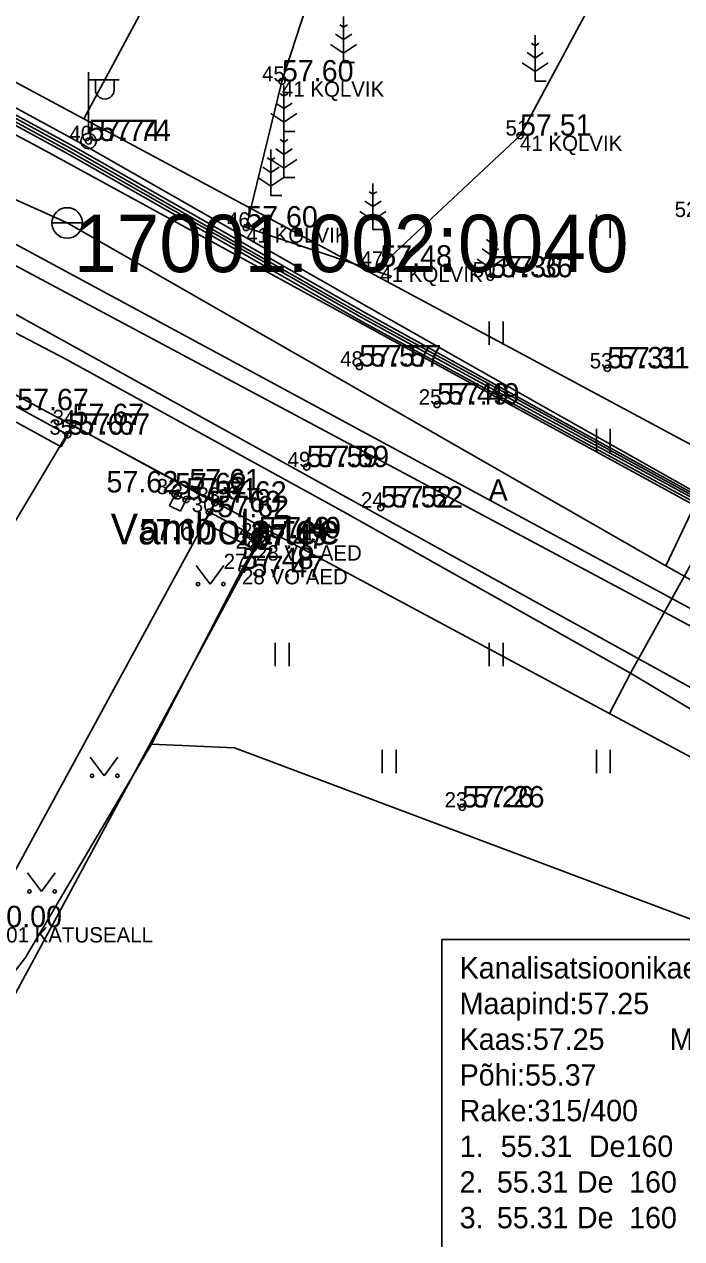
# Model space of a CAD drawing. Extents: x 640891 to 641083, y 6456526 to 6456669.
# Drawn here: x 640928.85 to 640950.33, y 6456556.9 to 6456596.6 of the extents above; entities that cross this region are included whole.
import ezdxf

# ---------------------------------------------------------------- set-up
doc = ezdxf.new("R2010")
doc.units = 0
for name, color, linetype in [('100koma2', 7, 'Continuous'), ('ABIJOONIS', 7, 'Continuous'), ('AED', 7, 'Continuous'), ('HALJASTUS', 7, 'Continuous'), ('KORGUS', 7, 'Continuous'), ('KPKAABEL', 7, 'Continuous'), ('KTRASS', 7, 'Continuous'), ('MOOTKORG', 7, 'Continuous'), ('MOOTMPUNKT', 7, 'Continuous'), ('MOOTNR', 7, 'Continuous'), ('MOOTPIIR', 7, 'Continuous'), ('MPKAABEL', 7, 'Continuous'), ('PIIR', 7, 'Continuous'), ('POST', 7, 'Continuous'), ('PUU', 7, 'Continuous'), ('SITRASS', 7, 'Continuous'), ('SKTRASS', 7, 'Continuous'), ('TEE', 7, 'Continuous'), ('VKAEV', 7, 'Continuous'), ('VTRASS', 7, 'Continuous')]:
    doc.layers.add(name, color=color, linetype=linetype)

msp = doc.modelspace()

# ---------------------------------------------------------------- linework, layer by layer
at = {"layer": 'ABIJOONIS'}
msp.add_lwpolyline([(640942.489, 6456566.685), (640951.949, 6456566.685), (640951.949, 6456555.319), (640942.489, 6456555.319)], close=True, dxfattribs=at)
at = {"layer": 'AED'}
for p, q in [((640920.739, 6456587.89), (640930.051, 6456582.793)), ((640930.051, 6456582.793), (640930.267, 6456583.186)), ((640933.59, 6456580.856), (640933.773, 6456581.238)), ((640933.59, 6456580.856), (640933.952, 6456580.683)), ((640933.952, 6456580.683), (640934.135, 6456581.065))]:
    msp.add_line(p, q, dxfattribs=at)
for points in [[(640930.267, 6456583.186), (640921.076, 6456588.216)], [(640930.267, 6456583.186), (640921.076, 6456588.216)], [(640934.135, 6456581.065), (640933.773, 6456581.238)], [(640936.327, 6456579.459), (640936.507, 6456579.796), (640934.895, 6456580.654), (640934.714, 6456580.318)], [(640936.327, 6456579.459), (640934.714, 6456580.318)], [(640936.397, 6456579.53), (640935.963, 6456578.793), (640933.007, 6456573.069)]]:
    msp.add_lwpolyline(points, dxfattribs=at)
at = {"layer": 'HALJASTUS'}
for p, q in [((640947.545, 6456590.381), (640947.545, 6456589.619)), ((640948, 6456590.381), (640948, 6456589.619)), ((640944.045, 6456586.881), (640944.045, 6456586.119)), ((640944.5, 6456586.881), (640944.5, 6456586.119)), ((640947.545, 6456583.381), (640947.545, 6456582.619)), ((640948, 6456583.381), (640948, 6456582.619)), ((640934.462, 6456578.908), (640934.925, 6456578.301)), ((640934.925, 6456578.301), (640935.371, 6456578.908)), ((640937.045, 6456576.381), (640937.045, 6456575.619)), ((640937.5, 6456576.381), (640937.5, 6456575.619)), ((640944.045, 6456576.381), (640944.045, 6456575.619)), ((640944.5, 6456576.381), (640944.5, 6456575.619)), ((640940.545, 6456572.881), (640940.545, 6456572.119)), ((640941, 6456572.881), (640941, 6456572.119)), ((640947.545, 6456572.881), (640947.545, 6456572.119)), ((640948, 6456572.881), (640948, 6456572.119)), ((640930.999, 6456572.642), (640931.462, 6456572.035)), ((640931.462, 6456572.035), (640931.908, 6456572.642)), ((640928.95, 6456568.859), (640929.413, 6456568.252)), ((640929.413, 6456568.252), (640929.859, 6456568.859))]:
    msp.add_line(p, q, dxfattribs=at)
msp.add_lwpolyline([(640940.859, 6456588.363), (640936.098, 6456589.959), (640937.267, 6456594.734), (640939.119, 6456600.434), (640944.153, 6456613.282), (640950.33, 6456623.315), (640954.177, 6456630.888), (640962.196, 6456639.436), (640963.998, 6456638.677), (640968.745, 6456632.01), (640966.503, 6456625.352), (640963.655, 6456626.075), (640962.794, 6456629.058), (640958.598, 6456629.914), (640954.818, 6456622.648), (640946.439, 6456612.875), (640948.12, 6456609.151), (640945.862, 6456604.895), (640949.763, 6456601.734), (640945.05, 6456592.964), (640940.483, 6456588.68)], dxfattribs=at)
for centre in [(640934.524, 6456578.301), (640935.353, 6456578.301), (640931.061, 6456572.035), (640931.89, 6456572.035), (640929.012, 6456568.252), (640929.841, 6456568.252)]:
    msp.add_circle(centre, 0.055, dxfattribs=at)
at = {"layer": 'KORGUS'}
for centre in [(640930.945, 6456592.786), (640944.075, 6456588.332), (640939.794, 6456585.413), (640947.904, 6456585.354), (640942.339, 6456584.172), (640930.423, 6456583.498), (640930.267, 6456583.186), (640938.078, 6456582.125), (640933.773, 6456581.238), (640934.135, 6456581.065), (640934.895, 6456580.654), (640935.08, 6456580.963), (640940.499, 6456580.804), (640936.327, 6456579.459), (640936.507, 6456579.796), (640943.159, 6456570.998)]:
    msp.add_circle(centre, 0.1, dxfattribs=at)
at = {"layer": 'KPKAABEL'}
msp.add_lwpolyline([(640977.507, 6456566.281), (640976.27, 6456566.95), (640967.49, 6456572.43), (640959.27, 6456576.625), (640951.05, 6456580.82), (640939.86, 6456586.9), (640935.075, 6456589.63), (640930.29, 6456592.36), (640924.23, 6456595.65), (640919.26, 6456598.135), (640914.117, 6456600.706)], dxfattribs=at)
at = {"layer": 'KTRASS'}
msp.add_lwpolyline([(640955.081, 6456575.091), (640928.16, 6456589.63)], dxfattribs=at)
at = {"layer": 'MOOTMPUNKT'}
for centre in [(640937.267, 6456594.734), (640945.05, 6456592.964), (640930.945, 6456592.786), (640936.098, 6456589.959), (640940.483, 6456588.68), (640944.075, 6456588.332), (640939.794, 6456585.413), (640947.904, 6456585.354), (640942.339, 6456584.172), (640930.423, 6456583.498), (640930.267, 6456583.186), (640938.078, 6456582.125), (640933.773, 6456581.238), (640934.135, 6456581.065), (640934.895, 6456580.654), (640935.08, 6456580.963), (640940.499, 6456580.804), (640936.327, 6456579.459), (640936.421, 6456579.57), (640936.507, 6456579.796), (640935.963, 6456578.793), (640943.159, 6456570.998)]:
    msp.add_circle(centre, 0.1, dxfattribs=at)
at = {"layer": 'MOOTPIIR'}
msp.add_lwpolyline([(640976.662, 6456538.007), (640959.29, 6456546.142), (640961.328, 6456555.553), (640965.053, 6456562.959), (640957.364, 6456564.816), (640935.712, 6456572.952), (640933.007, 6456573.069), (640928.881, 6456566.092), (640925.582, 6456561.827), (640921.958, 6456562.765), (640911.417, 6456572.885), (640912.029, 6456574.013), (640921.076, 6456588.216), (640912.945, 6456593.7), (640910.627, 6456595.318), (640915.929, 6456603.505), (640924.706, 6456598.502), (640938.233, 6456631.58)], dxfattribs=at)
at = {"layer": 'MPKAABEL'}
for points in [[(640914.394, 6456601.133), (640919.49, 6456598.58), (640924.46, 6456596.09), (640927.495, 6456594.445), (640930.53, 6456592.8), (640935.32, 6456590.07), (640940.11, 6456587.34), (640945.625, 6456584.22), (640951.14, 6456581.1), (640953.87, 6456579.745), (640956.6, 6456578.39), (640957.06, 6456579.17)], [(640914.173, 6456600.793), (640919.31, 6456598.225), (640924.28, 6456595.74), (640927.31, 6456594.095), (640930.34, 6456592.45), (640935.125, 6456589.72), (640939.91, 6456586.99), (640945.495, 6456583.945), (640951.08, 6456580.9), (640959.31, 6456576.71), (640967.54, 6456572.52), (640971.93, 6456569.78), (640976.32, 6456567.04), (640977.56, 6456566.369)], [(640977.608, 6456566.451), (640976.37, 6456567.12), (640971.98, 6456569.865), (640967.59, 6456572.61), (640959.355, 6456576.785), (640951.12, 6456580.96), (640945.54, 6456584.015), (640939.96, 6456587.07), (640935.175, 6456589.8), (640930.39, 6456592.53), (640927.355, 6456594.18), (640924.32, 6456595.83), (640919.35, 6456598.315), (640914.227, 6456600.876)], [(640977.66, 6456566.54), (640976.42, 6456567.21), (640972.03, 6456569.95), (640967.64, 6456572.69), (640959.395, 6456576.855), (640951.15, 6456581.02), (640945.58, 6456584.09), (640940.01, 6456587.16), (640935.225, 6456589.89), (640930.44, 6456592.62), (640927.405, 6456594.27), (640924.37, 6456595.92), (640919.4, 6456598.405), (640914.283, 6456600.963)]]:
    msp.add_lwpolyline(points, dxfattribs=at)
at = {"layer": 'PIIR'}
for points in [[(640930.79, 6456593.51), (640904.36, 6456607.7), (640935.64, 6456665.95), (640960.76, 6456649.34)], [(640957.22, 6456579.32), (640930.79, 6456593.51), (640960.76, 6456649.34), (640985.89, 6456632.73)]]:
    msp.add_lwpolyline(points, close=True, dxfattribs=at)
for points in [[(640890.598, 6456615.08), (640904.36, 6456607.7), (640930.79, 6456593.51), (640957.22, 6456579.32), (640983.63, 6456565.13), (641002.905, 6456555.058)], [(640993.023, 6456550.09), (640989.66, 6456551.83), (640963.18, 6456565.91), (640936.74, 6456580.1), (640910.31, 6456594.28), (640890.598, 6456604.875)], [(640890.598, 6456557.721), (640910.31, 6456594.28), (640936.74, 6456580.1), (640907.494, 6456525.865)], [(640907.494, 6456525.865), (640936.74, 6456580.1), (640963.18, 6456565.91), (640941.583, 6456525.865)]]:
    msp.add_lwpolyline(points, dxfattribs=at)
at = {"layer": 'POST'}
for p, q in [((640930.945, 6456593.036), (640930.945, 6456595.036)), ((640930.945, 6456594.786), (640931.945, 6456594.786)), ((640931.172, 6456594.465), (640931.172, 6456594.786)), ((640931.785, 6456594.465), (640931.785, 6456594.786)), ((640930.945, 6456592.786), (640930.945, 6456592.786))]:
    msp.add_line(p, q, dxfattribs=at)
msp.add_circle((640930.945, 6456592.786), 0.25, dxfattribs=at)
msp.add_arc((640931.478, 6456594.465), 0.306, 180, 0, dxfattribs=at)
at = {"layer": 'PUU'}
for p, q in [((640939.282, 6456596.856), (640939.282, 6456595.356)), ((640939.282, 6456596.106), (640939.016, 6456596.283)), ((640939.282, 6456596.506), (640939.158, 6456596.589)), ((640939.407, 6456596.589), (640939.282, 6456596.506)), ((640939.549, 6456596.283), (640939.282, 6456596.106)), ((640945.545, 6456596.249), (640945.545, 6456594.749)), ((640938.858, 6456595.945), (640939.282, 6456595.662)), ((640939.282, 6456595.662), (640939.707, 6456595.945)), ((640945.545, 6456595.899), (640945.42, 6456595.982)), ((640945.669, 6456595.982), (640945.545, 6456595.899)), ((640945.545, 6456595.499), (640945.278, 6456595.677)), ((640945.811, 6456595.677), (640945.545, 6456595.499)), ((640939.642, 6456595.356), (640939.282, 6456595.356)), ((640945.12, 6456595.339), (640945.545, 6456595.056)), ((640945.545, 6456595.056), (640945.969, 6456595.339)), ((640945.905, 6456594.749), (640945.545, 6456594.749)), ((640937.333, 6456594.249), (640937.209, 6456594.332)), ((640937.333, 6456594.599), (640937.333, 6456593.099)), ((640937.458, 6456594.332), (640937.333, 6456594.249)), ((640937.333, 6456593.849), (640937.066, 6456594.027)), ((640937.6, 6456594.027), (640937.333, 6456593.849)), ((640936.909, 6456593.688), (640937.333, 6456593.405)), ((640937.333, 6456593.405), (640937.757, 6456593.688)), ((640937.333, 6456593.099), (640937.333, 6456591.599)), ((640937.693, 6456593.099), (640937.333, 6456593.099)), ((640937.333, 6456592.749), (640937.209, 6456592.832)), ((640937.458, 6456592.832), (640937.333, 6456592.749)), ((640936.909, 6456592.16), (640936.784, 6456592.243)), ((640936.909, 6456592.51), (640936.909, 6456591.01)), ((640937.033, 6456592.243), (640936.909, 6456592.16)), ((640937.333, 6456592.349), (640937.066, 6456592.527)), ((640937.6, 6456592.527), (640937.333, 6456592.349)), ((640936.909, 6456591.76), (640936.642, 6456591.937)), ((640936.909, 6456592.188), (640937.333, 6456591.905)), ((640937.175, 6456591.937), (640936.909, 6456591.76)), ((640937.333, 6456591.905), (640937.757, 6456592.188)), ((640936.485, 6456591.599), (640936.909, 6456591.316)), ((640936.909, 6456591.316), (640937.333, 6456591.599)), ((640937.693, 6456591.599), (640937.333, 6456591.599)), ((640940.242, 6456591.048), (640940.118, 6456591.131)), ((640940.242, 6456591.398), (640940.242, 6456589.898)), ((640940.366, 6456591.131), (640940.242, 6456591.048)), ((640937.269, 6456591.01), (640936.909, 6456591.01)), ((640940.242, 6456590.648), (640939.975, 6456590.826)), ((640940.509, 6456590.826), (640940.242, 6456590.648)), ((640939.818, 6456590.487), (640940.242, 6456590.204)), ((640940.242, 6456590.204), (640940.666, 6456590.487)), ((640940.602, 6456589.898), (640940.242, 6456589.898)), ((640944.075, 6456589.482), (640943.951, 6456589.565)), ((640944.075, 6456589.832), (640944.075, 6456588.332)), ((640944.2, 6456589.565), (640944.075, 6456589.482)), ((640944.075, 6456589.082), (640943.809, 6456589.259)), ((640944.342, 6456589.259), (640944.075, 6456589.082)), ((640943.651, 6456588.921), (640944.075, 6456588.638)), ((640944.075, 6456588.638), (640944.5, 6456588.921)), ((640944.435, 6456588.332), (640944.075, 6456588.332))]:
    msp.add_line(p, q, dxfattribs=at)
at = {"layer": 'SITRASS'}
for points in [[(640972.09, 6456562.42), (640955.26, 6456571.44), (640948.66, 6456575.39), (640939.25, 6456580.69), (640930.23, 6456585.64), (640921.93, 6456589.97), (640913.28, 6456594.36)], [(640948.66, 6456575.39), (640951.34, 6456580.22), (640952.32, 6456581.95)], [(640948.66, 6456575.39), (640947.97, 6456574.07)]]:
    msp.add_lwpolyline(points, dxfattribs=at)
at = {"layer": 'SKTRASS'}
msp.add_lwpolyline([(640975.84, 6456563.446), (640963.035, 6456570.289), (640950.405, 6456577.04), (640931.282, 6456587.261), (640918.683, 6456593.994), (640912.062, 6456597.533)], dxfattribs=at)
at = {"layer": 'TEE'}
for points in [[(640977.461, 6456566.201), (640971.27, 6456569.61), (640958.74, 6456576.51), (640944.02, 6456584.555), (640929.3, 6456592.6), (640917.98, 6456598.615), (640914.098, 6456600.678)], [(640911.131, 6456596.096), (640915.765, 6456593.725), (640927.19, 6456587.88), (640941.825, 6456579.785), (640956.46, 6456571.69), (640969.135, 6456565.09), (640975.008, 6456562.032)], [(640927.641, 6456567.293), (640935.08, 6456580.963), (640930.423, 6456583.498), (640928.396, 6456580.096), (640927.415, 6456579.403), (640926.347, 6456578.97), (640924.212, 6456575.389), (640921.845, 6456575.967), (640920.143, 6456576.92), (640918.238, 6456578.393), (640916.853, 6456579.75), (640916.244, 6456580.63)]]:
    msp.add_lwpolyline(points, dxfattribs=at)
at = {"layer": 'VKAEV'}
msp.add_line((640929.747, 6456590.108), (640930.747, 6456590.108), dxfattribs=at)
msp.add_circle((640930.247, 6456590.108), 0.5, dxfattribs=at)
at = {"layer": 'VTRASS'}
for points in [[(640930.247, 6456590.108), (640926.576, 6456591.762)], [(640949.817, 6456578.894), (640930.247, 6456590.108)], [(640949.817, 6456578.894), (640951.07, 6456581.53)], [(640953.923, 6456576.584), (640949.817, 6456578.894)]]:
    msp.add_lwpolyline(points, dxfattribs=at)

# ---------------------------------------------------------------- texts
at = {"layer": '100koma2'}
for s, p in [('41 KQLVIK', (640937.267, 6456594.234)), ('41 KQLVIK', (640945.05, 6456592.464)), ('41 KQLVIK', (640936.098, 6456589.459)), ('41 KQLVIK', (640940.483, 6456588.18)), ('28 VO AED', (640936.421, 6456579.07)), ('28 VO AED', (640935.963, 6456578.293)), ('01 KATUSEALL', (640928.256, 6456566.583))]:
    msp.add_text(s, height=0.5, dxfattribs=at).set_placement(p)
at = {"layer": 'ABIJOONIS'}
for s, p in [('Kanalisatsioonikaev', (640943.077, 6456565.404)), ('Maapind:57.25', (640943.077, 6456564.238)), ('Kaas:57.25 ', (640943.077, 6456563.071)), ('Met', (640949.937, 6456563.071)), ('Põhi:55.37', (640943.077, 6456561.904)), ('Rake:315/400 ', (640943.077, 6456560.738)), ('1. ', (640943.077, 6456559.571)), ('55.31 ', (640944.419, 6456559.571)), ('De160 ', (640947.3, 6456559.571)), ('2. ', (640943.077, 6456558.404)), ('55.31 ', (640944.293, 6456558.404)), ('De ', (640946.909, 6456558.404)), ('160 ', (640948.615, 6456558.404)), ('3. ', (640943.077, 6456557.238)), ('55.31 ', (640944.293, 6456557.238)), ('De ', (640946.909, 6456557.238)), ('160 ', (640948.615, 6456557.238))]:
    msp.add_text(s, height=0.7, dxfattribs=at).set_placement(p)
at = {"layer": 'KORGUS'}
for s, p in [('57.74', (640931.295, 6456592.786)), ('57.36', (640944.425, 6456588.332)), ('57.57', (640940.144, 6456585.413)), ('57.31', (640948.254, 6456585.354)), ('57.67', (640928.613, 6456583.985)), ('57.49', (640942.689, 6456584.172)), ('57.67', (640930.617, 6456583.186)), ('57.59', (640938.428, 6456582.125)), ('57.62', (640931.532, 6456581.296)), ('57.61', (640934.24, 6456581.367)), ('57.62', (640935.157, 6456580.487)), ('57.52', (640940.849, 6456580.804)), ('57.60', (640932.616, 6456579.73)), ('57.49', (640936.857, 6456579.796)), ('57.47', (640936.271, 6456578.526)), ('57.26', (640943.509, 6456570.998))]:
    msp.add_text(s, height=0.7, dxfattribs=at).set_placement(p)
at = {"layer": 'MOOTKORG'}
for s, p in [('57.60', (640937.267, 6456594.734)), ('57.74', (640930.945, 6456592.786)), ('57.51', (640945.05, 6456592.964)), ('57.60', (640936.098, 6456589.959)), ('57.48', (640940.483, 6456588.68)), ('57.36', (640944.075, 6456588.332)), ('57.57', (640939.794, 6456585.413)), ('57.31', (640947.904, 6456585.354)), ('57.49', (640942.339, 6456584.172)), ('57.67', (640930.423, 6456583.498)), ('57.67', (640930.267, 6456583.186)), ('57.59', (640938.078, 6456582.125)), ('57.62', (640933.773, 6456581.238)), ('57.61', (640934.135, 6456581.065)), ('57.62', (640935.08, 6456580.963)), ('57.60', (640934.895, 6456580.654)), ('57.52', (640940.499, 6456580.804)), ('57.49', (640936.507, 6456579.796)), ('57.47', (640936.327, 6456579.459)), ('57.49', (640936.421, 6456579.57)), ('57.48', (640935.963, 6456578.793)), ('57.26', (640943.159, 6456570.998)), ('0.00', (640928.256, 6456567.083))]:
    msp.add_text(s, height=0.7, dxfattribs=at).set_placement(p)
at = {"layer": 'MOOTNR'}
for s, p in [('45', (640936.617, 6456594.734)), ('51', (640944.575, 6456592.964)), ('40', (640930.32, 6456592.786)), ('52', (640950.104, 6456590.303)), ('46', (640935.473, 6456589.959)), ('47', (640939.833, 6456588.68)), ('50', (640943.5, 6456588.332)), ('48', (640939.169, 6456585.413)), ('53', (640947.329, 6456585.354)), ('25', (640941.739, 6456584.172)), ('34', (640929.773, 6456583.498)), ('35', (640929.667, 6456583.186)), ('49', (640937.453, 6456582.125)), ('32', (640933.173, 6456581.238)), ('31', (640933.66, 6456581.065)), ('30', (640934.32, 6456580.654)), ('33', (640934.506, 6456580.963)), ('24', (640939.849, 6456580.804)), ('28', (640935.752, 6456579.459)), ('26', (640935.846, 6456579.57)), ('29', (640935.932, 6456579.796)), ('27', (640935.363, 6456578.793)), ('23', (640942.584, 6456570.998))]:
    msp.add_text(s, height=0.5, dxfattribs=at).set_placement(p)
at = {"layer": 'PIIR'}
for s, height, p in [('17001:002:0040', 1.875, (640930.47, 6456588.5)), ('Vambola tee', 1.00002, (640931.67, 6456579.6))]:
    msp.add_text(s, height=height, dxfattribs=at).set_placement(p)
at = {"layer": 'TEE'}
msp.add_text('A', height=0.7, dxfattribs=at).set_placement((640944.023, 6456581.03))

doc.saveas('drawing.dxf')
